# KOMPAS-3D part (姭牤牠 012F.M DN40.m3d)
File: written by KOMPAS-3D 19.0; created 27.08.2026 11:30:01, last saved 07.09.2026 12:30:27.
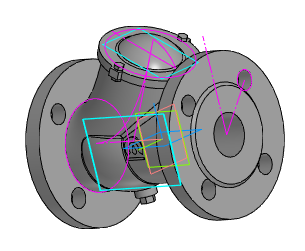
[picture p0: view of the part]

Document properties: Автор: Энергия; Полное имя файла: Z:\3.Личные\kachalov\001_3d для проектировщиков\х.х Тип 012F\012F.M\Клапан 012F.M DN40.m3d

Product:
- Part/product: (unnamed)  | designation Клапан 012F.M DN40
    Масса: 11.1374

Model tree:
1. Эскиз:1
2. Элемент вращения:1
     Угол 1 = 360
3. Эскиз:2  (with: Элемент вращения:1)
4. Перпендикулярная плоскость:1
5. Эскиз:3
6. Эскиз:12  (with: Элемент вращения:1)
7. Элемент по сечениям:1
8. Эскиз:7
9. Элемент выдавливания:2
     Расстояние 2 = 8
10. Эскиз:9  (with: Элемент выдавливания:2)
11. Элемент вращения:2  (with: Элемент выдавливания:2)
     Угол 1 = 360
12. Эскиз:10  (with: Элемент вращения:1)
13. Элемент выдавливания:3  (with: Элемент вращения:1)
     Расстояние 2 = 16
14. Массив по концентрической сетке:1  (with: Элемент выдавливания:3, Эскиз:10, Элемент вращения:1)  (4 pattern instances)
     Шаг 2 = 360
15. Эскиз:11  (with: Элемент вращения:1)
16. Элемент выдавливания:4  (with: Элемент вращения:1)
     Расстояние 2 = 16
17. Массив по концентрической сетке:2  (with: Элемент выдавливания:4, Эскиз:11, Элемент вращения:1)  (4 pattern instances)
     Шаг 2 = 360
18. Скругление:6  (with: Элемент вращения:2)
     Радиус = 3
19. Эскиз:13  (with: Элемент выдавливания:2, Скругление:6)
20. Элемент выдавливания:5  (with: Элемент выдавливания:2)
     Расстояние 1 = 3.5; Расстояние 2 = 11.5; Смещение 2 = 3.5
21. Зеркальный массив:3
22. Экземпляр ( 1 )
23. Экземпляр ( 2 )  (with: Элемент выдавливания:5)
24. Касательная плоскость:1  (with: Элемент вращения:1)
     Угол = 90
25. Смещенная плоскость:1
     Расстояние = 1
26. Эскиз:14
27. Элемент выдавливания:6  (with: Элемент вращения:1)
     Расстояние 1 = -1.00056; Расстояние 2 = 1
28. Эскиз:15  (with: Элемент вращения:1)
29. Элемент вращения:3
     Угол 1 = 360
30. Скругление:10  (with: Элемент вращения:3, Элемент по сечениям:1)
     Радиус = 5
31. Эскиз:16
32. Элемент выдавливания:7
     Расстояние 1 = 50
33. Эскиз:17  (with: Элемент выдавливания:7)
34. Элемент выдавливания:8
     Расстояние 1 = 6.5
35. Эскиз:18  (with: Элемент вращения:1, Элемент по сечениям:1)
36. Элемент выдавливания:9
     Расстояние 2 = 180

Expressions: Dn/2; D/2; D2/2; D2/2-5; 360/(2*n); 360/(n*2); D2-6; D2-5; D2+5; (D2+5)/2
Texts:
  Клапан 012F.M DN40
